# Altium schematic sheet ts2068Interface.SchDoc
size A; SheetNumber: 2; SheetTotal: 5
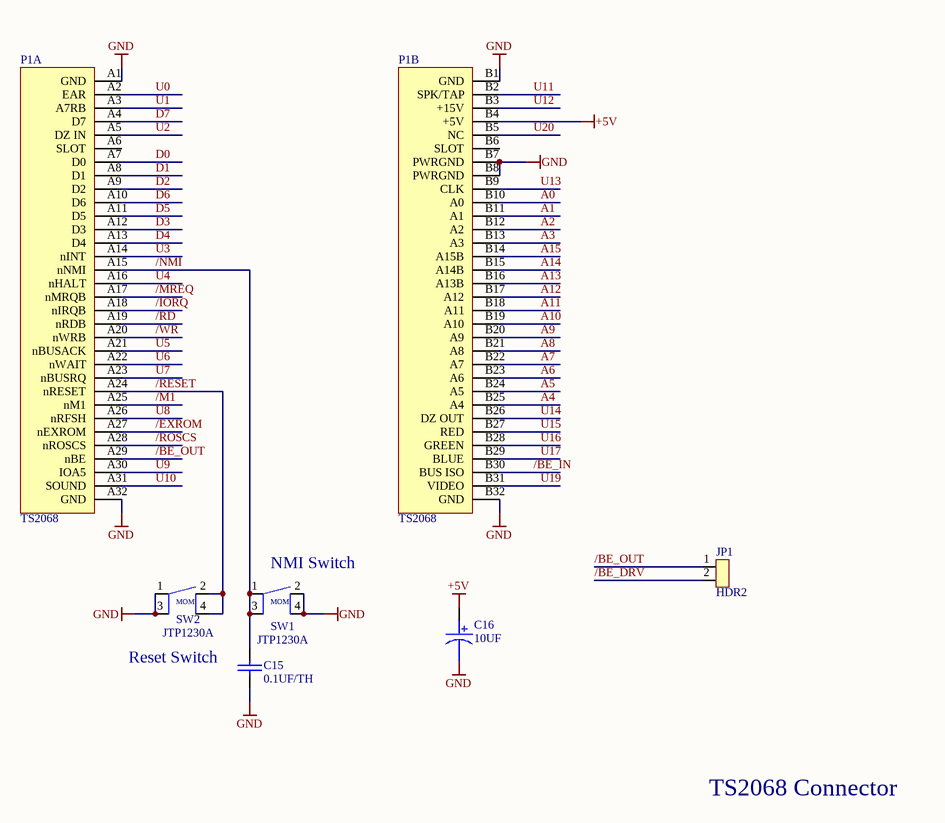
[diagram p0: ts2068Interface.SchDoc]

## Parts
C15  0.1UF/TH  [CAPH5]
C16  10UF  [CAP10EL]
JP1  HDR2  [HDR2]
P1  TS2068  [TS2068A]  (parts A,B of 2)
SW1  JTP1230A  [TACSW_6.5x4.5]
SW2  JTP1230A  [TACSW_6.5x4.5]

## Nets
+5V: C16.1 P1.B4(+5V)
GND: C15.1 C16.2 P1.A1(GND) P1.A32(GND) P1.B1(GND) P1.B7(PWRGND) P1.B8(PWRGND) P1.B32(GND) SW1.2 SW1.4 SW2.1 SW2.3
/BE_DRV: JP1.2
/BE_IN: P1.B30(BUS_ISO)
/BE_OUT: JP1.1 P1.A29(nBE)
/EXROM: P1.A27(nEXROM)
/IORQ: P1.A18(nIRQB)
/M1: P1.A25(nM1)
/MREQ: P1.A17(nMRQB)
/NMI: C15.2 P1.A15(nNMI) SW1.1 SW1.3
/RD: P1.A19(nRDB)
/RESET: P1.A24(nRESET) SW2.2 SW2.4
/ROSCS: P1.A28(nROSCS)
/WR: P1.A20(nWRB)
A0: P1.B10(A0)
A1: P1.B11(A1)
A2: P1.B12(A2)
A3: P1.B13(A3)
A4: P1.B25(A4)
A5: P1.B24(A5)
A6: P1.B23(A6)
A7: P1.B22(A7)
A8: P1.B21(A8)
A9: P1.B20(A9)
A10: P1.B19(A10)
A11: P1.B18(A11)
A12: P1.B17(A12)
A13: P1.B16(A13B)
A14: P1.B15(A14B)
A15: P1.B14(A15B)
D0: P1.A7(D0)
D1: P1.A8(D1)
D2: P1.A9(D2)
D3: P1.A12(D3)
D4: P1.A13(D4)
D5: P1.A11(D5)
D6: P1.A10(D6)
D7: P1.A4(D7)
U0: P1.A2(EAR)
U1: P1.A3(A7RB)
U2: P1.A5(DZ_IN)
U3: P1.A14(nINT)
U4: P1.A16(nHALT)
U5: P1.A21(nBUSACK)
U6: P1.A22(nWAIT)
U7: P1.A23(nBUSRQ)
U8: P1.A26(nRFSH)
U9: P1.A30(IOA5)
U10: P1.A31(SOUND)
U11: P1.B2(SPK/TAP)
U12: P1.B3(+15V)
U13: P1.B9(CLK)
U14: P1.B26(DZ_OUT)
U15: P1.B27(RED)
U16: P1.B28(GREEN)
U17: P1.B29(BLUE)
U19: P1.B31(VIDEO)
U20: P1.B5(NC)

Not connected (* = marked no-connect by the designer): P1 A6(SLOT) B6(SLOT)

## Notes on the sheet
- (near SW1) NMI Switch
- (near C15) Reset Switch
- TS2068 Connector

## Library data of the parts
C15 = 0.1UF/TH: 0.1 µF ±10% 50V Ceramic Capacitor X7R Radial; MFG: Vishay; MFG PN: K104K10X7RF5UH5; DK PN: BC2665CT-ND
C16 = 10UF: CAP ALUM 10UF 20% 16V RADIAL; MFG: Panasonic; MFG PN: ECE-A1CKA100; DK PN: P807-ND
SW1 SW2 = JTP1230A: Tactile Switch SPST-NO Top Actuated Through Hole; MFG: Apem; DK PN: 679-2429-ND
